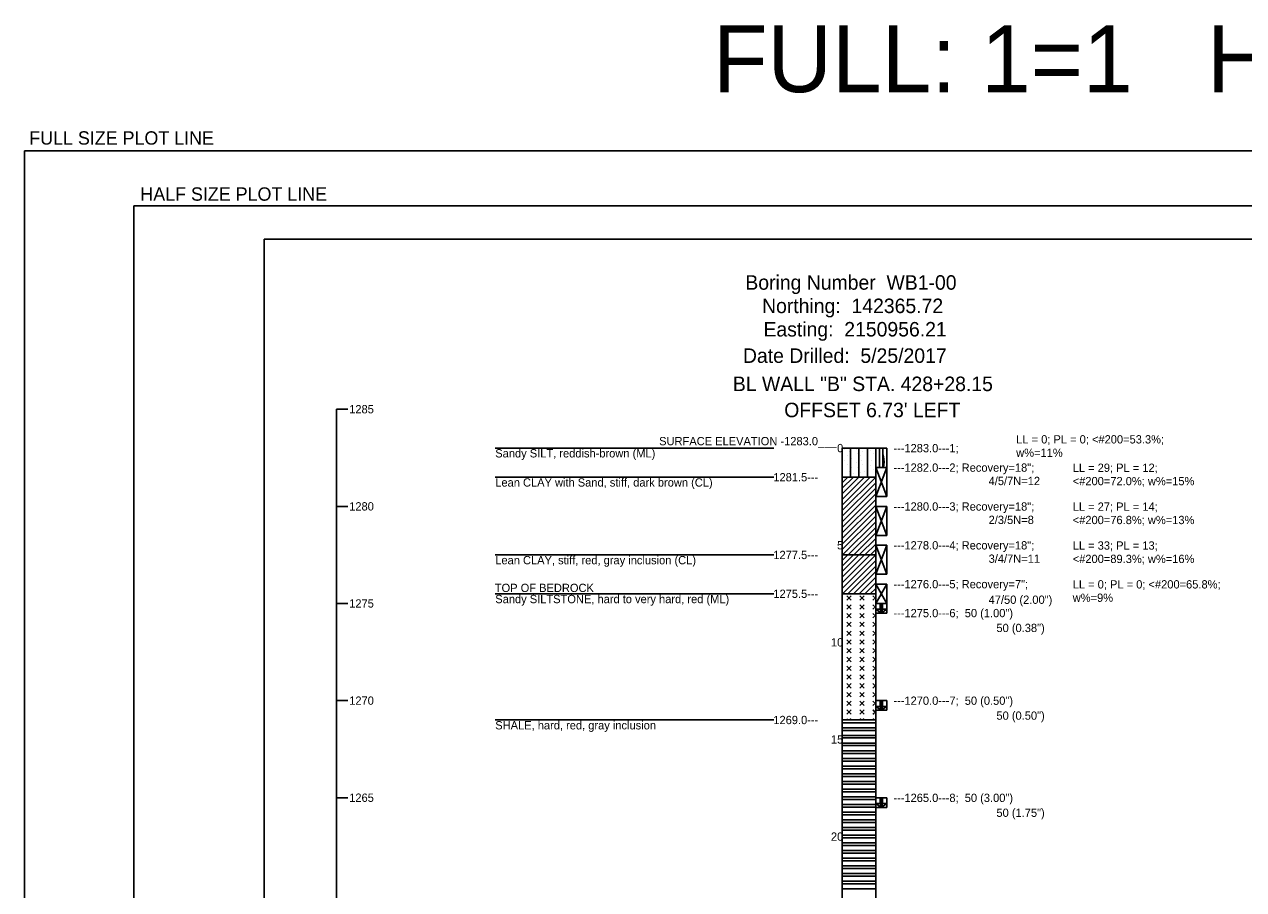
# Model space of a CAD drawing. Extents: x 7 to 126, y 24 to 56.
# Drawn here: x 6.62 to 24.87, y 42.91 to 55.86 of the extents above; entities that cross this region are included whole.
import ezdxf

# ---------------------------------------------------------------- set-up
doc = ezdxf.new("R2010")
doc.units = 0
for name, color, linetype in [('S', 7, 'Continuous'), ('SHT_Plot_Shape_Full', 7, 'Continuous'), ('SHT_Plot_Shape_Half', 7, 'Continuous'), ('SHT_Sheet_Border', 7, 'Continuous')]:
    doc.layers.add(name, color=color, linetype=linetype)

# ---------------------------------------------------------------- blocks, each defined once
blk = doc.blocks.new('POINT_DISPLAY')
blk.add_line((0, 0), (0, 0))

msp = doc.modelspace()

# ---------------------------------------------------------------- linework, layer by layer
msp.add_line((11.298, 37.021), (11.298, 50.103))
for points in [[(11.298, 50.103), (11.464, 50.103)], [(13.672, 49.521), (17.839, 49.521)], [(18.866, 49.521), (18.866, 38.475)], [(18.866, 49.521), (19.366, 49.521)], [(18.991, 49.085), (18.991, 49.521)], [(19.116, 49.085), (19.116, 49.521)], [(19.241, 49.085), (19.241, 49.521)], [(19.366, 49.521), (19.533, 49.521)], [(19.366, 49.521), (19.366, 38.475)], [(19.533, 49.231), (19.533, 49.521)], [(19.366, 49.231), (19.533, 49.231)], [(19.366, 49.231), (19.533, 48.795)], [(19.366, 48.795), (19.533, 49.231)], [(19.366, 49.231), (19.533, 49.231)], [(19.533, 48.795), (19.533, 49.231)], [(13.672, 49.085), (17.839, 49.085)], [(18.866, 49.085), (19.366, 49.085)], [(18.866, 49.002), (18.949, 49.085)], [(18.866, 48.919), (19.033, 49.085)], [(18.866, 48.835), (19.116, 49.085)], [(18.866, 48.752), (19.199, 49.085)], [(18.866, 48.669), (19.283, 49.085)], [(18.866, 48.585), (19.366, 49.085)], [(18.866, 48.502), (19.366, 49.002)], [(18.866, 48.419), (19.366, 48.919)], [(18.866, 48.335), (19.366, 48.835)], [(18.866, 48.252), (19.366, 48.752)], [(19.366, 48.795), (19.533, 48.795)], [(11.298, 48.649), (11.464, 48.649)], [(18.866, 48.169), (19.366, 48.669)], [(18.866, 48.085), (19.366, 48.585)], [(19.366, 48.649), (19.533, 48.213)], [(19.366, 48.213), (19.533, 48.649)], [(19.366, 48.649), (19.533, 48.649)], [(19.533, 48.213), (19.533, 48.649)], [(18.866, 48.002), (19.366, 48.502)], [(18.87, 47.922), (19.366, 48.419)], [(18.953, 47.922), (19.366, 48.335)], [(19.037, 47.922), (19.366, 48.252)], [(19.366, 48.213), (19.533, 48.213)], [(19.12, 47.922), (19.366, 48.169)], [(19.203, 47.922), (19.366, 48.085)], [(19.287, 47.922), (19.366, 48.002)], [(19.366, 48.068), (19.533, 47.632)], [(19.366, 47.632), (19.533, 48.068)], [(19.366, 48.068), (19.533, 48.068)], [(19.533, 47.632), (19.533, 48.068)], [(13.672, 47.922), (17.839, 47.922)], [(18.866, 47.922), (19.366, 47.922)], [(18.866, 47.839), (18.949, 47.922)], [(18.866, 47.756), (19.033, 47.922)], [(18.866, 47.672), (19.116, 47.922)], [(18.866, 47.589), (19.199, 47.922)], [(18.866, 47.506), (19.283, 47.922)], [(18.866, 47.422), (19.366, 47.922)], [(18.868, 47.341), (19.366, 47.839)], [(18.951, 47.341), (19.366, 47.756)], [(19.035, 47.341), (19.366, 47.672)], [(19.366, 47.632), (19.533, 47.632)], [(19.118, 47.341), (19.366, 47.589)], [(19.201, 47.341), (19.366, 47.506)], [(19.366, 47.486), (19.533, 47.196)], [(19.366, 47.196), (19.533, 47.486)], [(19.366, 47.486), (19.533, 47.486)], [(19.533, 47.196), (19.533, 47.486)], [(13.672, 47.341), (17.839, 47.341)], [(18.866, 47.341), (19.366, 47.341)], [(18.997, 47.308), (18.932, 47.243)], [(18.932, 47.308), (18.997, 47.243)], [(19.194, 47.308), (19.129, 47.243)], [(19.129, 47.308), (19.194, 47.243)], [(19.285, 47.341), (19.366, 47.422)], [(19.325, 47.308), (19.366, 47.268)], [(19.366, 47.283), (19.325, 47.243)], [(11.298, 47.196), (11.464, 47.196)], [(18.997, 47.177), (18.932, 47.111)], [(18.932, 47.177), (18.997, 47.111)], [(19.194, 47.177), (19.129, 47.111)], [(19.129, 47.177), (19.194, 47.111)], [(19.325, 47.177), (19.366, 47.136)], [(19.366, 47.152), (19.325, 47.111)], [(19.366, 47.196), (19.533, 47.196)], [(19.366, 47.196), (19.533, 47.196)], [(19.533, 47.05), (19.533, 47.196)], [(18.997, 47.046), (18.932, 46.98)], [(18.932, 47.046), (18.997, 46.98)], [(18.997, 46.915), (18.932, 46.849)], [(18.932, 46.915), (18.997, 46.849)], [(19.194, 47.046), (19.129, 46.98)], [(19.129, 47.046), (19.194, 46.98)], [(19.194, 46.915), (19.129, 46.849)], [(19.129, 46.915), (19.194, 46.849)], [(19.325, 47.046), (19.366, 47.005)], [(19.366, 47.021), (19.325, 46.98)], [(19.325, 46.915), (19.366, 46.874)], [(19.366, 47.05), (19.533, 47.05)], [(18.997, 46.783), (18.932, 46.718)], [(18.932, 46.783), (18.997, 46.718)], [(19.194, 46.783), (19.129, 46.718)], [(19.129, 46.783), (19.194, 46.718)], [(19.366, 46.89), (19.325, 46.849)], [(19.325, 46.783), (19.366, 46.743)], [(19.366, 46.758), (19.325, 46.718)], [(18.997, 46.652), (18.932, 46.586)], [(18.932, 46.652), (18.997, 46.586)], [(19.194, 46.652), (19.129, 46.586)], [(19.129, 46.652), (19.194, 46.586)], [(19.325, 46.652), (19.366, 46.611)], [(19.366, 46.627), (19.325, 46.586)], [(18.997, 46.521), (18.932, 46.455)], [(18.932, 46.521), (18.997, 46.455)], [(18.997, 46.39), (18.932, 46.324)], [(18.932, 46.39), (18.997, 46.324)], [(19.194, 46.521), (19.129, 46.455)], [(19.129, 46.521), (19.194, 46.455)], [(19.194, 46.39), (19.129, 46.324)], [(19.129, 46.39), (19.194, 46.324)], [(19.325, 46.521), (19.366, 46.48)], [(19.366, 46.496), (19.325, 46.455)], [(19.325, 46.39), (19.366, 46.349)], [(19.366, 46.365), (19.325, 46.324)], [(18.997, 46.258), (18.932, 46.193)], [(18.932, 46.258), (18.997, 46.193)], [(19.194, 46.258), (19.129, 46.193)], [(19.129, 46.258), (19.194, 46.193)], [(19.325, 46.258), (19.366, 46.218)], [(19.366, 46.233), (19.325, 46.193)], [(18.997, 46.127), (18.932, 46.062)], [(18.932, 46.127), (18.997, 46.062)], [(18.997, 45.996), (18.932, 45.93)], [(18.932, 45.996), (18.997, 45.93)], [(19.194, 46.127), (19.129, 46.062)], [(19.129, 46.127), (19.194, 46.062)], [(19.194, 45.996), (19.129, 45.93)], [(19.129, 45.996), (19.194, 45.93)], [(19.325, 46.127), (19.366, 46.086)], [(19.366, 46.102), (19.325, 46.062)], [(19.325, 45.996), (19.366, 45.955)], [(18.997, 45.865), (18.932, 45.799)], [(18.932, 45.865), (18.997, 45.799)], [(19.194, 45.865), (19.129, 45.799)], [(19.129, 45.865), (19.194, 45.799)], [(19.366, 45.971), (19.325, 45.93)], [(19.325, 45.865), (19.366, 45.824)], [(19.366, 45.84), (19.325, 45.799)], [(11.298, 45.742), (11.464, 45.742)], [(18.997, 45.733), (18.932, 45.668)], [(18.932, 45.733), (18.997, 45.668)], [(19.194, 45.733), (19.129, 45.668)], [(19.129, 45.733), (19.194, 45.668)], [(19.325, 45.733), (19.366, 45.693)], [(19.366, 45.709), (19.325, 45.668)], [(19.366, 45.742), (19.533, 45.742)], [(19.533, 45.597), (19.533, 45.742)], [(13.672, 45.452), (17.839, 45.452)], [(18.866, 45.452), (19.366, 45.452)], [(18.866, 45.452), (19.366, 45.452)], [(18.997, 45.602), (18.932, 45.537)], [(18.932, 45.602), (18.997, 45.537)], [(18.932, 45.471), (18.951, 45.452)], [(18.997, 45.471), (18.978, 45.452)], [(19.194, 45.602), (19.129, 45.537)], [(19.129, 45.602), (19.194, 45.537)], [(19.129, 45.471), (19.148, 45.452)], [(19.194, 45.471), (19.175, 45.452)], [(19.325, 45.602), (19.327, 45.601), (19.366, 45.562)], [(19.366, 45.577), (19.34, 45.551), (19.325, 45.537)], [(19.325, 45.471), (19.345, 45.452)], [(19.366, 45.597), (19.533, 45.597)], [(18.866, 45.412), (19.366, 45.412)], [(18.866, 45.337), (19.366, 45.337)], [(18.866, 45.297), (19.366, 45.297)], [(18.866, 45.222), (19.366, 45.222)], [(18.866, 45.183), (19.366, 45.183)], [(18.866, 45.107), (19.366, 45.107)], [(18.866, 45.068), (19.366, 45.068)], [(18.866, 44.992), (19.366, 44.992)], [(18.866, 44.953), (19.366, 44.953)], [(18.866, 44.877), (19.366, 44.877)], [(18.866, 44.838), (19.366, 44.838)], [(18.866, 44.763), (19.366, 44.763)], [(18.866, 44.723), (19.366, 44.723)], [(18.866, 44.648), (19.366, 44.648)], [(18.866, 44.608), (19.366, 44.608)], [(18.866, 44.533), (19.366, 44.533)], [(18.866, 44.494), (19.366, 44.494)], [(18.866, 44.418), (19.366, 44.418)], [(18.866, 44.379), (19.366, 44.379)], [(11.298, 44.289), (11.464, 44.289)], [(18.866, 44.303), (19.366, 44.303)], [(18.866, 44.264), (19.366, 44.264)], [(18.866, 44.188), (19.366, 44.188)], [(19.366, 44.289), (19.533, 44.289)], [(19.533, 44.143), (19.533, 44.289)], [(18.866, 44.149), (19.366, 44.149)], [(18.866, 44.074), (19.366, 44.074)], [(18.866, 44.034), (19.366, 44.034)], [(19.366, 44.143), (19.533, 44.143)], [(18.866, 43.959), (19.366, 43.959)], [(18.866, 43.919), (19.366, 43.919)], [(18.866, 43.844), (19.366, 43.844)], [(18.866, 43.805), (19.366, 43.805)], [(18.866, 43.729), (19.366, 43.729)], [(18.866, 43.69), (19.366, 43.69)], [(18.866, 43.614), (19.366, 43.614)], [(18.866, 43.575), (19.366, 43.575)], [(18.866, 43.499), (19.366, 43.499)], [(18.866, 43.46), (19.366, 43.46)], [(18.866, 43.385), (19.366, 43.385)], [(18.866, 43.345), (19.366, 43.345)], [(18.866, 43.27), (19.366, 43.27)], [(18.866, 43.23), (19.366, 43.23)], [(18.866, 43.155), (19.366, 43.155)], [(18.866, 43.116), (19.366, 43.116)], [(18.866, 43.04), (19.366, 43.04)], [(18.866, 43.001), (19.366, 43.001)], [(18.866, 42.925), (19.366, 42.925)]]:
    msp.add_lwpolyline(points)
for points in [[(19.424, 49.521), (19.424, 49.231), (19.474, 49.231), (19.474, 49.521)], [(19.489, 49.355), (19.483, 49.396), (19.474, 49.436), (19.489, 49.355)], [(19.474, 49.436), (19.474, 49.231), (19.489, 49.355), (19.474, 49.436)], [(19.474, 49.231), (19.489, 49.271), (19.489, 49.355), (19.474, 49.231)], [(19.474, 49.231), (19.483, 49.231), (19.489, 49.271), (19.474, 49.231)], [(19.489, 49.271), (19.491, 49.313), (19.489, 49.355), (19.489, 49.271)], [(19.433, 47.109), (19.366, 47.109), (19.449, 47.05), (19.433, 47.109)], [(19.433, 47.109), (19.466, 47.109), (19.466, 47.196), (19.433, 47.109)], [(19.433, 47.109), (19.466, 47.196), (19.433, 47.196), (19.433, 47.109)], [(19.433, 47.109), (19.449, 47.05), (19.466, 47.109), (19.433, 47.109)], [(19.449, 47.05), (19.533, 47.109), (19.466, 47.109), (19.449, 47.05)], [(19.433, 45.655), (19.366, 45.655), (19.449, 45.597), (19.433, 45.655)], [(19.433, 45.655), (19.466, 45.655), (19.466, 45.742), (19.433, 45.655)], [(19.433, 45.655), (19.466, 45.742), (19.433, 45.742), (19.433, 45.655)], [(19.433, 45.655), (19.449, 45.597), (19.466, 45.655), (19.433, 45.655)], [(19.449, 45.597), (19.533, 45.655), (19.466, 45.655), (19.449, 45.597)], [(19.433, 44.202), (19.366, 44.202), (19.449, 44.143), (19.433, 44.202)], [(19.433, 44.202), (19.466, 44.202), (19.466, 44.289), (19.433, 44.202)], [(19.433, 44.202), (19.466, 44.289), (19.433, 44.289), (19.433, 44.202)], [(19.433, 44.202), (19.449, 44.143), (19.466, 44.202), (19.433, 44.202)], [(19.449, 44.143), (19.533, 44.202), (19.466, 44.202), (19.449, 44.143)]]:
    msp.add_lwpolyline(points, close=True)
at = {"layer": 'SHT_Plot_Shape_Full'}
msp.add_lwpolyline([(6.624, 53.971), (42.624, 53.971), (42.624, 29.971), (6.624, 29.971)], close=True, dxfattribs=at)
at = {"layer": 'SHT_Plot_Shape_Half'}
msp.add_lwpolyline([(8.262, 53.146), (42.262, 53.146), (42.262, 31.146), (8.262, 31.146)], close=True, dxfattribs=at)
at = {"layer": 'SHT_Sheet_Border'}
msp.add_lwpolyline([(10.212, 52.646), (41.712, 52.646), (41.712, 31.646), (10.212, 31.646)], close=True, dxfattribs=at)

# ---------------------------------------------------------------- block references
at = {"xscale": 0.01, "yscale": 0.01}
for p in [(18.905, 49.505), (18.972, 49.471), (19.072, 49.505), (19.172, 49.471), (19.292, 49.488), (18.872, 49.438), (18.905, 49.338), (18.939, 49.405), (18.939, 49.271), (19.005, 49.371), (19.072, 49.305), (19.095, 49.441), (19.139, 49.405), (19.155, 49.329), (19.172, 49.271), (19.239, 49.405), (19.305, 49.338), (19.339, 49.438), (18.872, 49.205), (18.972, 49.171), (19.005, 49.238), (19.039, 49.138), (19.09, 49.227), (19.105, 49.105), (19.142, 49.158), (19.205, 49.171), (19.29, 49.253), (19.339, 49.205), (18.872, 49.002), (18.905, 49.069), (18.939, 48.969), (18.972, 49.035), (19.005, 48.935), (19.072, 49.069), (19.095, 49.005), (19.139, 48.969), (19.339, 49.002), (18.872, 48.769), (18.905, 48.902), (18.939, 48.835), (18.972, 48.735), (19.005, 48.802), (19.072, 48.869), (19.09, 48.791), (19.339, 48.769), (18.872, 48.569), (18.939, 48.635), (19.039, 48.702), (19.072, 48.602), (19.105, 48.669), (19.142, 48.722), (18.905, 48.502), (18.905, 48.402), (18.972, 48.535), (18.972, 48.369), (19.072, 48.402), (19.105, 48.469), (19.139, 48.535), (18.872, 48.335), (18.905, 48.235), (18.939, 48.302), (19.005, 48.269), (19.072, 48.202), (19.095, 48.338), (19.139, 48.302), (19.339, 48.335), (18.872, 48.102), (18.939, 48.169), (18.972, 48.069), (19.005, 48.135), (19.039, 48.035), (19.09, 48.125), (19.105, 48.002), (19.142, 48.055), (19.339, 48.102), (18.939, 47.969), (19.072, 47.935)]:
    msp.add_blockref('POINT_DISPLAY', p, dxfattribs=at)

# ---------------------------------------------------------------- texts
for s, height, p in [('Boring Number  WB1-00', 0.217, (17.415, 51.891)), ('Northing:  142365.72', 0.217, (17.665, 51.541)), ('Easting:  2150956.21', 0.217, (17.686, 51.191)), ('Date Drilled:  5/25/2017', 0.217, (17.379, 50.796)), ('BL WALL "B" STA. 428+28.15', 0.217, (17.228, 50.374)), ("OFFSET 6.73' LEFT", 0.217, (17.997, 49.983)), ('1285', 0.124, (11.486, 50.041)), ('SURFACE ELEVATION -1283.0___', 0.124, (16.125, 49.563)), ('LL = 0; PL = 0; <#200=53.3%;', 0.124, (21.469, 49.59)), ('Sandy SILT, reddish-brown (ML)', 0.124, (13.672, 49.381)), ('0', 0.124, (18.788, 49.459)), ('---1283.0---1;', 0.124, (19.63, 49.458)), ('w%=11%', 0.124, (21.469, 49.39)), ('---1282.0---2; Recovery=18";', 0.124, (19.63, 49.167)), ('LL = 29; PL = 12;', 0.124, (22.315, 49.165)), ('1281.5---', 0.124, (17.834, 49.023)), ('4/5/7N=12', 0.124, (21.056, 48.967)), ('<#200=72.0%; w%=15%', 0.124, (22.315, 48.965)), ('Lean CLAY with Sand, stiff, dark brown (CL)', 0.124, (13.672, 48.945)), ('1280', 0.124, (11.486, 48.587)), ('---1280.0---3; Recovery=18";', 0.124, (19.63, 48.585)), ('LL = 27; PL = 14;', 0.124, (22.315, 48.583)), ('2/3/5N=8', 0.124, (21.056, 48.385)), ('<#200=76.8%; w%=13%', 0.124, (22.315, 48.383)), ('5', 0.124, (18.788, 48.006)), ('---1278.0---4; Recovery=18";', 0.124, (19.63, 48.004)), ('LL = 33; PL = 13;', 0.124, (22.315, 48.001)), ('Lean CLAY, stiff, red, gray inclusion (CL)', 0.124, (13.672, 47.782)), ('1277.5---', 0.124, (17.834, 47.86)), ('3/4/7N=11', 0.124, (21.056, 47.804)), ('<#200=89.3%; w%=16%', 0.124, (22.315, 47.801)), ('TOP OF BEDROCK', 0.124, (13.665, 47.367)), ('---1276.0---5; Recovery=7";', 0.124, (19.63, 47.423)), ('LL = 0; PL = 0; <#200=65.8%;', 0.124, (22.315, 47.42)), ('Sandy SILTSTONE, hard to very hard, red (ML)', 0.124, (13.672, 47.2)), ('1275.5---', 0.124, (17.834, 47.279)), ('47/50 (2.00")', 0.124, (21.056, 47.19)), ('w%=9%', 0.124, (22.315, 47.22)), ('1275', 0.124, (11.486, 47.134)), ('---1275.0---6;  50 (1.00")', 0.124, (19.63, 46.99)), ('50 (0.38")', 0.124, (21.173, 46.768)), ('10', 0.124, (18.696, 46.552)), ('1270', 0.124, (11.486, 45.68)), ('---1270.0---7;  50 (0.50")', 0.124, (19.63, 45.679)), ('SHALE, hard, red, gray inclusion', 0.124, (13.672, 45.311)), ('1269.0---', 0.124, (17.834, 45.39)), ('50 (0.50")', 0.124, (21.173, 45.456)), ('15', 0.124, (18.696, 45.099)), ('1265', 0.124, (11.486, 44.227)), ('---1265.0---8;  50 (3.00")', 0.124, (19.63, 44.225)), ('50 (1.75")', 0.124, (21.173, 44.002)), ('20', 0.124, (18.696, 43.645))]:
    msp.add_text(s, height=height).set_placement(p)
at = {"layer": 'DEFPOINTS'}
for s, p in [('FULL SIZE PLOT LINE', (6.697, 54.062)), ('HALF SIZE PLOT LINE', (8.36, 53.223))]:
    msp.add_text(s, height=0.2, dxfattribs=at).set_placement(p)
at = {"layer": 'S'}
msp.add_text('FULL: 1=1   HALF: 1=2', height=1, dxfattribs=at).set_placement((16.93, 54.847))

doc.saveas('drawing.dxf')
